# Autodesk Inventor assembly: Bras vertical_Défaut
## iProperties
Shininess: 64.0
Length Units: 11269
Angle Units: 11279
Time Units: 11290
Mass Units: 11283
Length Display Precision: 3
Angle Display Precision: 2
Compacted: True
Created: 2006-11
Part Number: Bras vertical_Défaut
Document SubType Name: Assembly
Designer: profs_sti
Density: 0.0
Volumn: 0.0
Area: 0.0
PropertySet Name: Model Information
Control State: 0
Master: False
Checked Out: False
Author: profs_sti
